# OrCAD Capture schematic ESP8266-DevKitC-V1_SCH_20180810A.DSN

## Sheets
1 01_FunctionBlock: title: 00_FunctionBlock; rev: V1
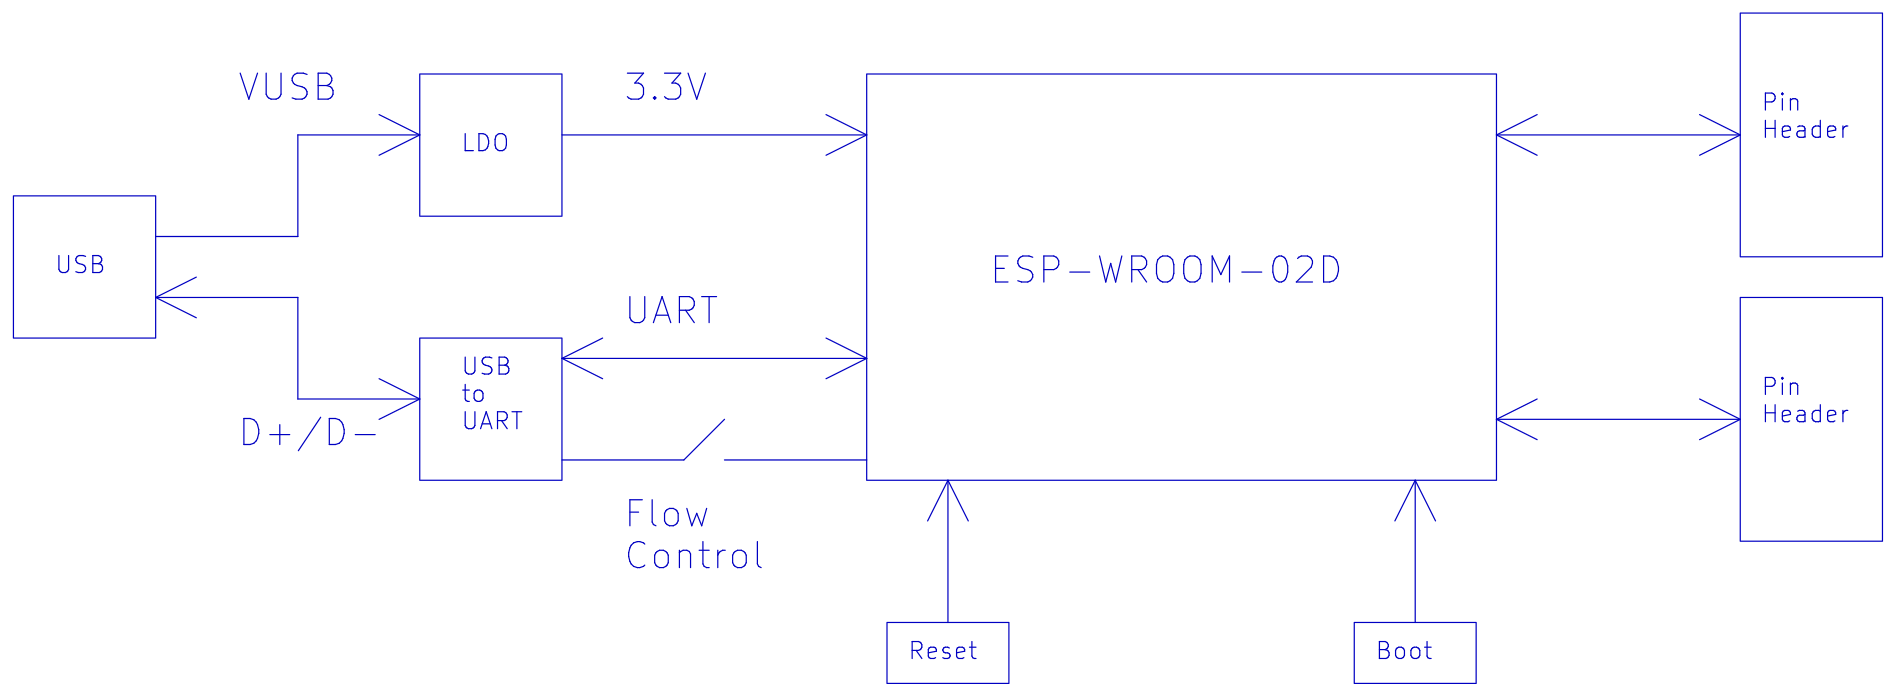
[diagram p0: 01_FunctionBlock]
2 02_ESP8266_DevKitC_V1: size C; title: 01_ESP8266_DevKitC_V1
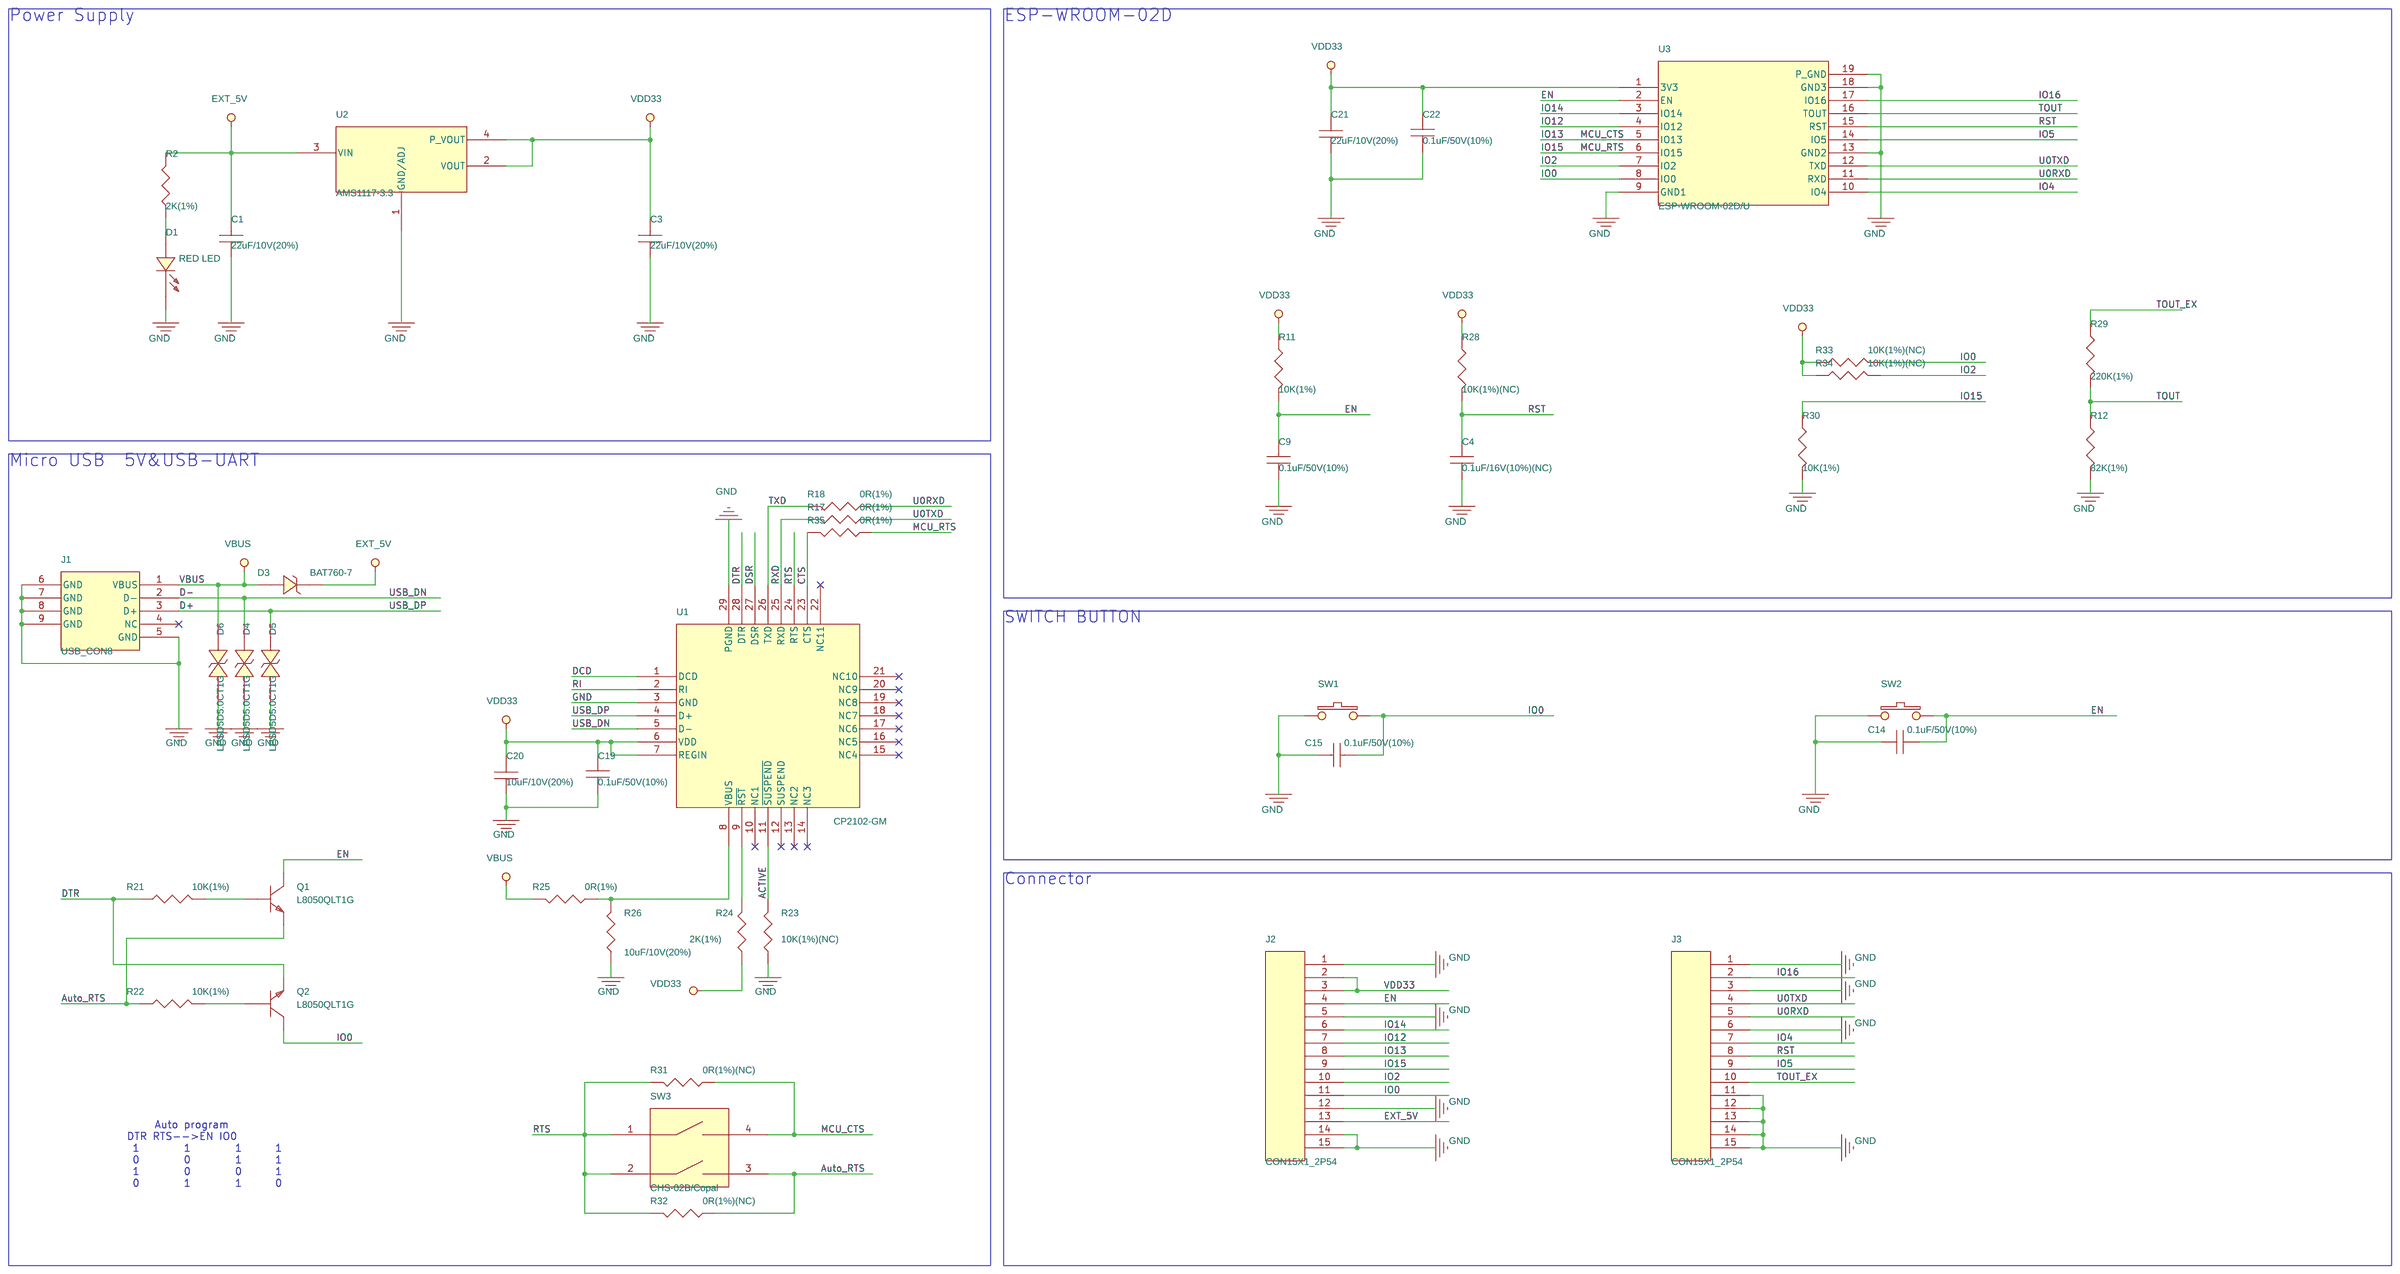
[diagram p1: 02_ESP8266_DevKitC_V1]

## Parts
C1  22uF/10V(20%)  [C0603]
C3  22uF/10V(20%)  [C0603]
C4  0.1uF/16V(10%)(NC)  [C0402]
C9  0.1uF/50V(10%)  [C0402]
C14  0.1uF/50V(10%)  [C0402]
C15  0.1uF/50V(10%)  [C0402]
C19  0.1uF/50V(10%)  [C0402]
C20  10uF/10V(20%)  [C0402]
C21  22uF/10V(20%)  [C0603]
C22  0.1uF/50V(10%)  [C0402]
D1  RED LED  [LED0603]
D3  BAT760-7  [SOD323]
D4  LESD5D5.0CT1G  [SOD-523]
D5  LESD5D5.0CT1G  [SOD-523]
D6  LESD5D5.0CT1G  [SOD-523]
J1  USB_CON8  [USB_5P]
J2  CON15X1_2P54  [CON15X1_2P54]
J3  CON15X1_2P54  [CON15X1_2P54]
Q1  L8050QLT1G  [SOT-23-3]
Q2  L8050QLT1G  [SOT-23-3]
R2  2K(1%)  [R0402]
R11  10K(1%)  [R0402]
R12  82K(1%)  [R0402]
R17  0R(1%)  [R0402]
R18  0R(1%)  [R0402]
R21  10K(1%)  [R0402]
R22  10K(1%)  [R0402]
R23  10K(1%)(NC)  [R0402]
R24  2K(1%)  [R0402]
R25  0R(1%)  [R0402]
R26  10uF/10V(20%)  [R0402]
R28  10K(1%)(NC)  [R0402]
R29  220K(1%)  [R0402]
R30  10K(1%)  [R0402]
R31  0R(1%)(NC)  [R0402]
R32  0R(1%)(NC)  [R0402]
R33  10K(1%)(NC)  [R0402]
R34  10K(1%)(NC)  [R0402]
R35  0R(1%)  [R0402]
SW1  SW PUSHBUTTON  [SW_3X4X2MM]
SW2  SW PUSHBUTTON  [SW_3X4X2MM]
SW3  CHS-02B/Copal  [DipSwtich_SMT_2x2_1P27]
U1  CP2102-GM  [CP2102_QFN_28P]
U2  AMS1117-3.3  [SOT-223]
U3  ESP-WROOM-02D/U  [ESP-WROOM-02]

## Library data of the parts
C1 C3 C4 C9 C14 C15 C19-C22 = CAP_NP
D1 = LED_1
D3 = DIODE_POWER_0
D4-D6 = DIODE_BI-DIR_TRIG: Options: ESD
J1 = CON4_2
J2 J3 = CON15X1_2P54
Q1 Q2 = NPN_BCE_0
R2 R11 R12 R28-R30 R33 R34 = RESISTOR_0
R17 R18 R25 R31 R32 R35 = RESISTOR_0: SIGNAL_MODEL: DEFAULT_RESISTOR_10000OHM_1_2
R21-R24 R26 = RESISTOR_0: SIGNAL_MODEL: DEFAULT_RESISTOR_200OHM_1_2
SW1 SW2 = SW_PUSHBUTTON
SW3 = DipSwtich_SMT_2x2_1P27
U1 = CP2102_QFN_28
U2 = NCP1117_0
U3 = ESP_WROOM_0

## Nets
GND: C1.1 C3.1 C4.2 C9.2 C14.1 C15.1 C19.2 C20.1 C21.1 C22.2 D1.2(CATHODE) D4.2 D5.2 D6.2 J1.5(GND) J1.6(GND) J1.7(GND) J1.8(GND) J1.9(GND) J2.1 J2.5 J2.12 J2.14 J2.15 J3.1 J3.3 J3.6 J3.11 J3.12 J3.13 J3.14 J3.15 R12.2 R23.1 R26.1 R30.2 SW1.1 SW2.1 U1.3(GND) U1.29(PGND) U2.1(GND/ADJ) U3.9(GND1) U3.13(GND2) U3.18(GND3) U3.19(P_GND)
VBUS: D3.2 D6.1 J1.1(VBUS) R25.2
VDD33: C3.2 C19.1 C20.2 C21.2 C22.1 J2.2 J2.3 R11.1 R24.1 R28.1 R33.1 R34.1 U1.6(VDD) U1.7(REGIN) U2.2(VOUT) U2.4(P_VOUT) U3.1(3V3)
ACTIVE: R23.2 U1.11(~{SUSPEND})
Auto_RTS: Q1.2(E) R22.1 R32.1 SW3.3
CTS: R35.2 U1.23(CTS)
D+: D5.1 J1.3(D+) U1.4(D+)
D-: D4.1 J1.2(D-) U1.5(D-)
DCD: U1.1(DCD)
DSR: U1.27(DSR)
DTR: Q2.2(E) R21.1 U1.28(DTR)
EN: C9.1 C14.2 J2.4 Q1.3(C) R11.2 SW2.2 U3.2(EN)
EXT_5V: C1.2 D3.1 J2.13 R2.1 U2.3(VIN)
IO0: C15.2 J2.11 Q2.3(C) R33.2 SW1.2 U3.8(IO0)
IO2: J2.10 R34.2 U3.7(IO2)
IO4: J3.7 U3.10(IO4)
IO5: J3.9 U3.14(IO5)
IO12: J2.7 U3.4(IO12)
IO13: J2.8 R31.1 SW3.4 U3.5(IO13)
IO14: J2.6 U3.3(IO14)
IO15: J2.9 R30.1 R35.1 U3.6(IO15)
IO16: J3.2 U3.17(IO16)
RI: U1.2(RI)
RST: C4.1 J3.8 R28.2 U3.15(RST)
RTS: R31.2 R32.2 SW3.1 SW3.2 U1.24(RTS)
RXD: R17.2 U1.25(RXD)
TOUT: R12.1 R29.2 U3.16(TOUT)
TOUT_EX: J3.10 R29.1
TXD: R18.2 U1.26(TXD)
U0RXD: J3.5 R18.1 U3.11(RXD)
U0TXD: J3.4 R17.1 U3.12(TXD)
N16505834: Q2.1(B) R22.2
N16505838: Q1.1(B) R21.2
N16507634: R25.1 R26.2 U1.8(VBUS)
N16522975: D1.1(ANODE) R2.2
N16660617: R24.2 U1.9(~{RST})

Not connected (* = marked no-connect by the designer): J1 4(NC)*; U1 10(NC1)* 12(SUSPEND)* 13(NC2)* 14(NC3)* 15(NC4)* 16(NC5)* 17(NC6)* 18(NC7)* 19(NC8)* 20(NC9)* 21(NC10)* 22(NC11)*

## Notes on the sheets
sheet 1
- VUSB
- 3.3V
- Pin
  Header
- LDO
- USB
- ESP-WROOM-02D
- UART
- USB
  to
  UART
- Pin
  Header
- D+/D-
- Flow
  Control
- Reset
- Boot
sheet 2
- Power Supply
- ESP-WROOM-02D
- Micro USB  5V&USB-UART
- SWITCH BUTTON
- Connector
- Auto program
  DTR RTS-->EN IO0
   1        1        1      1
   0        0        1      1
   1        0        0      1
   0        1        1      0
